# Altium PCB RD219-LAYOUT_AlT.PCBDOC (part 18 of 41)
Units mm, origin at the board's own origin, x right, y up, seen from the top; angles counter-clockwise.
Board outline 209.75 x 159.97 mm, 2 copper layers (TOP, BOTTOM), stack 0 mm thick; 398 components, 199 nets, 1469 pads, 0 vias.
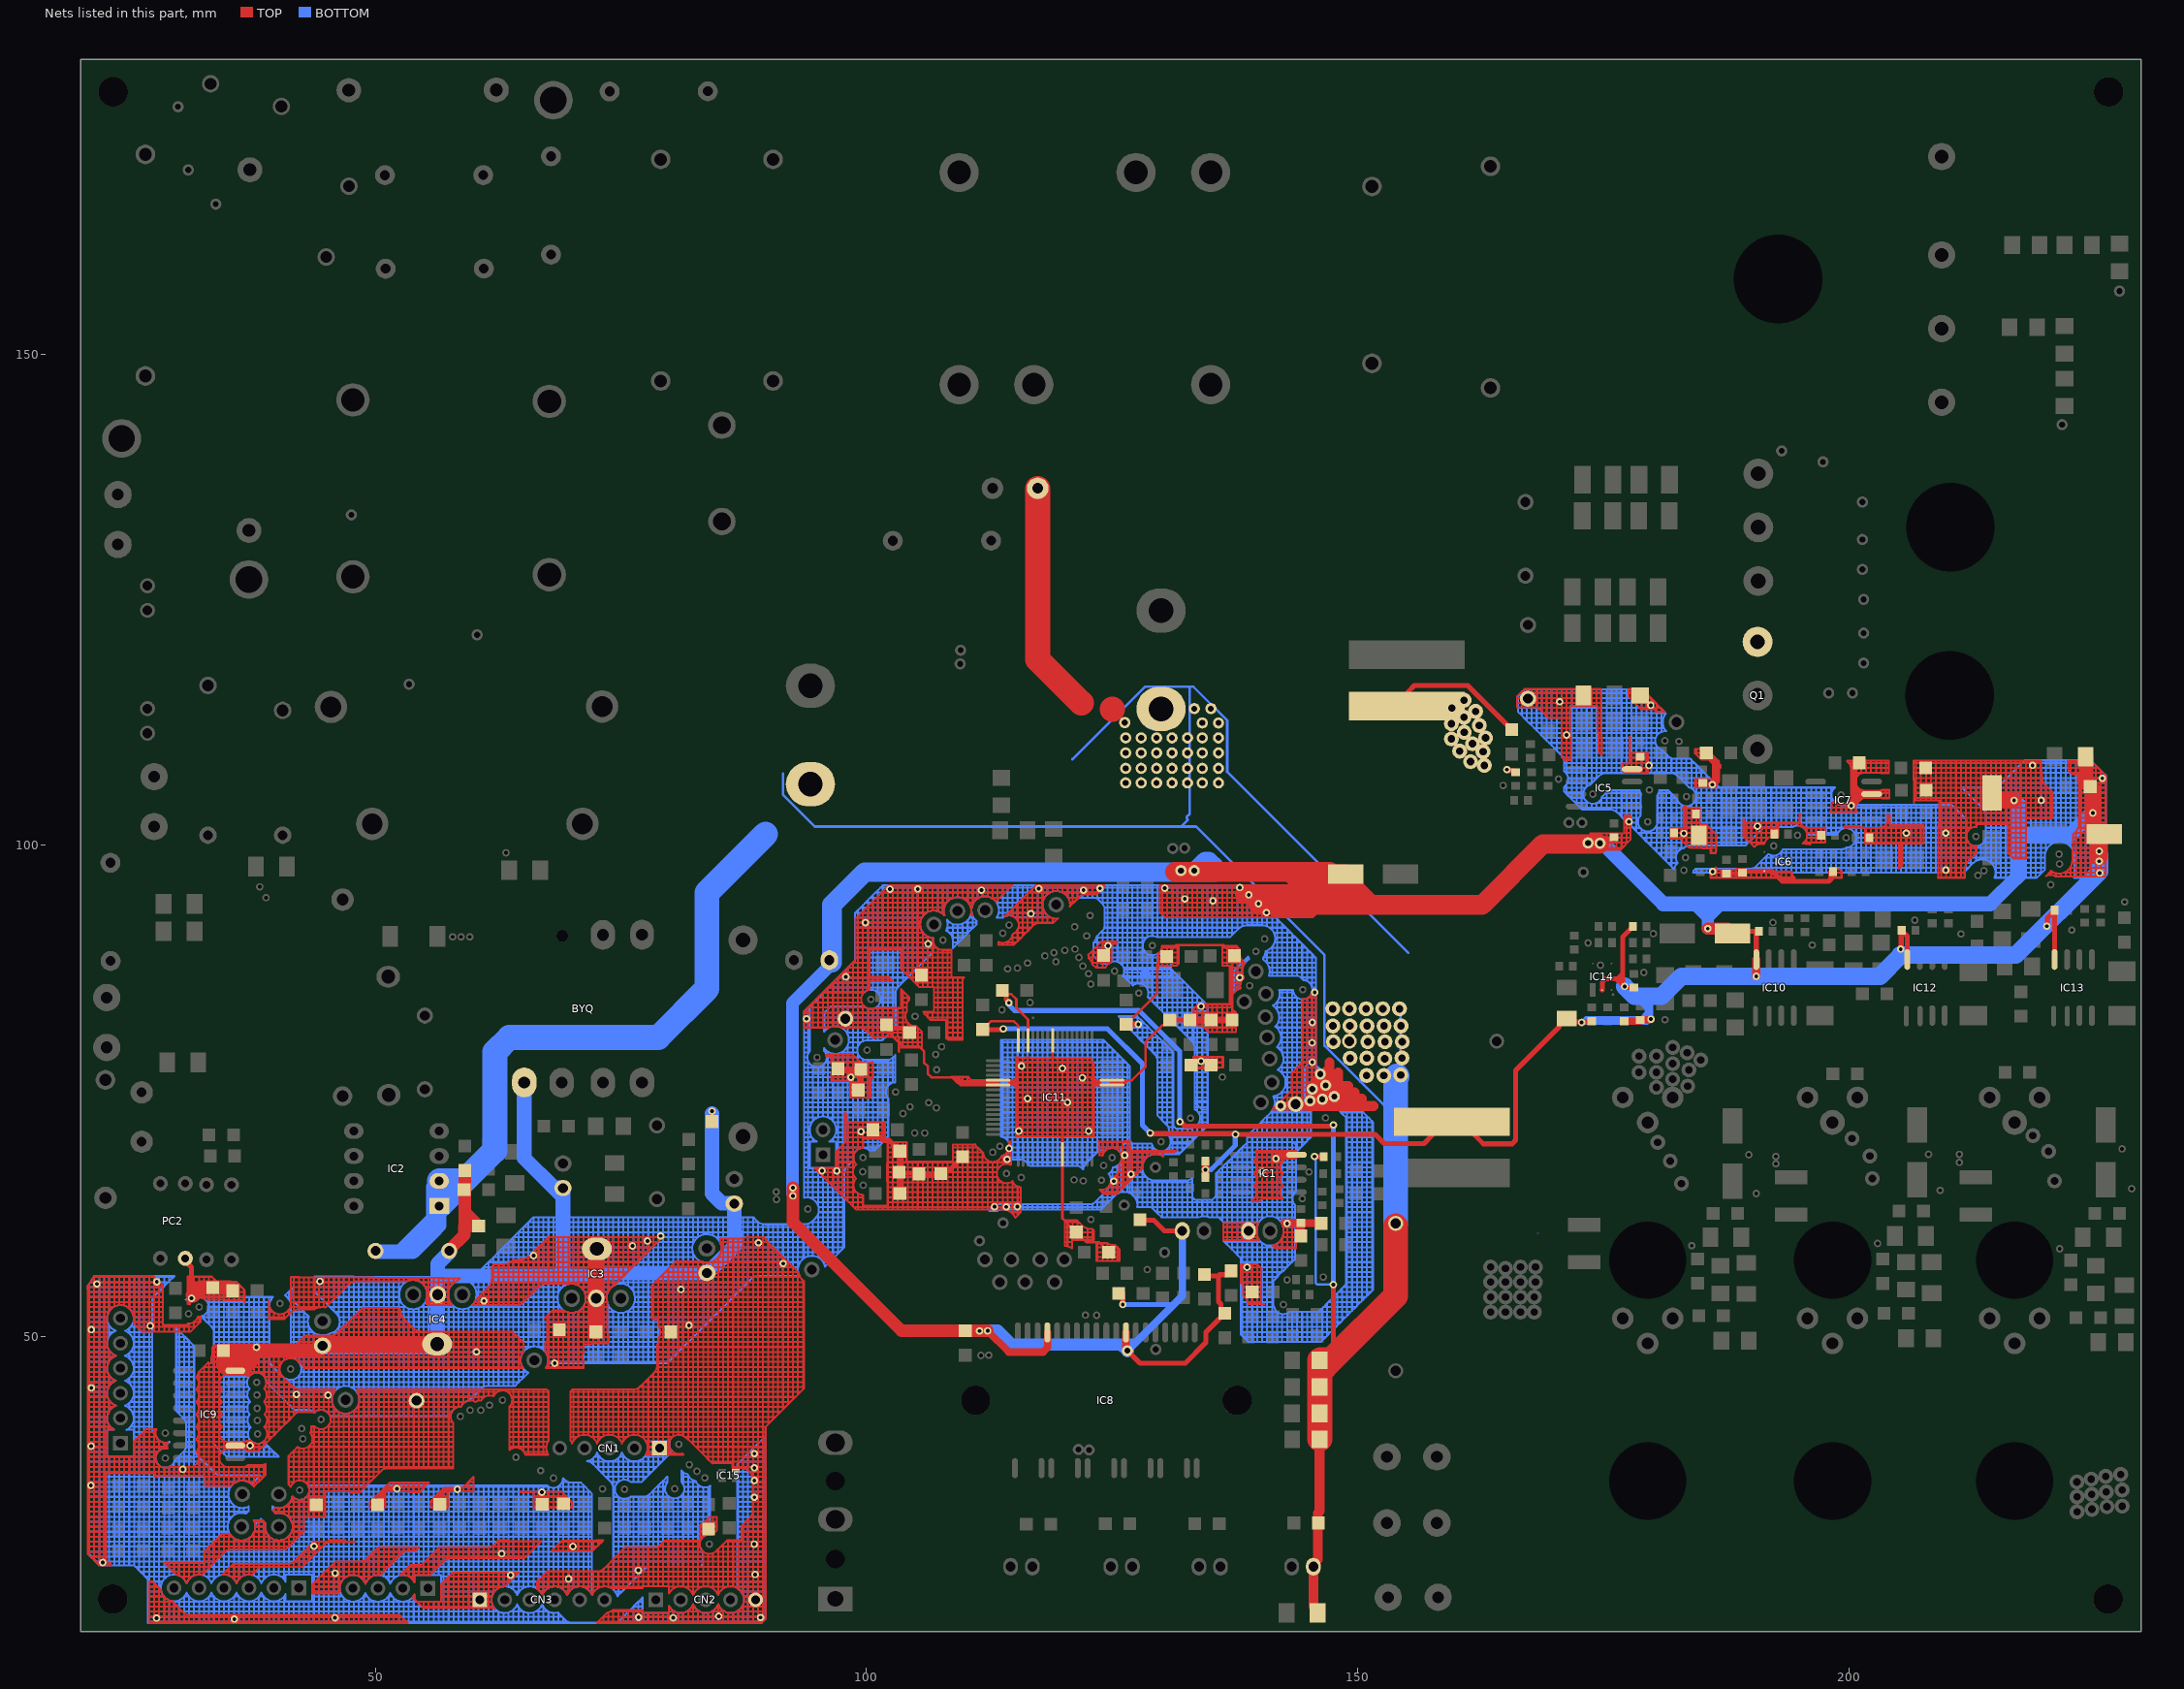
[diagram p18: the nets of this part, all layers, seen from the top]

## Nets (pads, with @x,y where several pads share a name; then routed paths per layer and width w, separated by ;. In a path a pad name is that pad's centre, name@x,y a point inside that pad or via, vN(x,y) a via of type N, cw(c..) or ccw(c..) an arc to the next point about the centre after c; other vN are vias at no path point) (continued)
GND: (continued)
  TOP w0.203: 223.073,101.39 cw(c222.057,102.282) 223.013,101.326 ccw(c222.057,102.282) 223.073,101.39 ; 223.073,101.39 ccw(c222.057,102.282) 223.315,101.788 ; 223.073,101.39 ccw(c222.057,102.282) 223.315,101.788 ; 223.073,107.231 223.073,107.376 ; 223.073,107.231 223.309,107.231 223.309,106.868 ; 223.073,107.376 223.073,107.884 ; 223.073,107.376 223.581,107.376 ; 223.073,107.884 223.073,108.392 ; 223.073,107.884 223.581,107.884 ; 223.073,108.392 ZD4.1@223.581,108.392 ; 223.073,108.392 223.073,108.631 ; 223.073,108.631 ZD4.1@223.581,108.631 ; 223.309,106.868 223.581,106.868 ; 223.315,101.788 ccw(c222.057,102.282) 223.409,102.282 ; 223.315,101.788 ccw(c222.057,102.282) 223.409,102.282 ; 223.315,101.788 223.581,101.788 ; 223.354,106.36 cw(c222.057,105.979) 223.409,105.979 ; 223.354,106.36 ccw(c222.057,105.979) 223.31,106.485 cw(c222.057,105.979) 223.354,106.36 ; 223.354,106.36 cw(c222.057,105.979) 223.409,105.979 ; 223.354,106.36 223.581,106.36 ; 223.409,102.282 223.409,102.296 ; 223.409,102.296 223.409,102.804 ; 223.409,102.296 223.581,102.296 ; 223.409,102.804 223.581,102.804 ; 223.409,102.804 223.409,103.312 ; 223.409,103.312 223.581,103.312 ; 223.409,103.312 223.409,103.82 ; 223.409,103.82 223.581,103.82 ; 223.409,103.82 223.409,104.328 ; 223.409,104.328 223.581,104.328 ; 223.409,104.328 223.409,104.836 ; 223.409,104.836 223.581,104.836 ; 223.409,104.836 223.409,105.344 ; 223.409,105.344 223.409,105.852 ; 223.409,105.344 223.581,105.344 ; 223.409,105.852 223.581,105.852 ; 223.409,105.852 223.409,105.979 ; 223.581,96.853 224.089,96.853 ; 223.581,96.853 223.581,97.216 ; 223.581,97.216 223.581,97.724 ; 223.581,97.216 224.089,97.216 ; 223.581,97.724 223.581,98.232 ; 223.581,97.724 224.089,97.724 ; 223.581,98.232 223.581,98.74 ; 223.581,98.232 224.089,98.232 ; 223.581,98.74 224.089,98.74 ; 223.581,98.74 223.581,99.248 ; 223.581,99.248 224.089,99.248 ; 223.581,99.248 223.581,99.756 ; 223.581,99.756 223.581,100.264 ; 223.581,99.756 224.089,99.756 ; 223.581,100.264 223.581,100.772 ; 223.581,100.264 224.089,100.264 ; 223.581,100.772 223.581,101.28 ; 223.581,100.772 224.089,100.772 ; 223.581,101.28 223.581,101.788 ; 223.581,101.28 224.089,101.28 ; 223.581,101.788 223.581,102.296 ; 223.581,101.788 224.089,101.788 ; 223.581,102.296 223.581,102.804 ; 223.581,102.296 224.089,102.296 ; 223.581,102.804 223.581,103.312 ; 223.581,102.804 224.089,102.804 ; 223.581,103.312 223.581,103.82 ; 223.581,103.312 224.089,103.312 ; 223.581,103.82 223.581,104.328 ; 223.581,103.82 224.089,103.82 ; 223.581,104.328 223.581,104.836 ; 223.581,104.328 224.089,104.328 ; 223.581,104.836 223.581,105.344 ; 223.581,104.836 224.089,104.836 ; 223.581,105.344 223.581,105.852 ; 223.581,105.344 C57.2@224.089,105.344 ; 223.581,105.852 223.581,106.36 ; 223.581,105.852 C57.2@224.089,105.852 ; 223.581,106.36 223.581,106.868 ; 223.581,106.36 C57.2@224.089,106.36 ; 223.581,106.868 223.581,107.376 ; 223.581,106.868 224.089,106.868 ; 223.581,107.376 223.581,107.884 ; 223.581,107.376 224.089,107.376 ; 223.581,107.884 ZD4.1@223.581,108.392 ; 223.581,107.884 224.089,107.884 ; ZD4.1@223.581,108.392 ZD4.1@223.581,108.631 ; ZD4.1@223.581,108.392 ZD4.1@224.089,108.392 ; ZD4.1@223.581,108.631 ZD4.1@224.089,108.631 ; 224.089,96.853 224.597,96.853 ; 224.089,96.853 224.089,97.216 ; 224.089,97.216 224.089,97.724 ; 224.089,97.216 224.597,97.216 ; 224.089,97.724 224.089,98.232 ; 224.089,97.724 224.597,97.724 ; 224.089,98.232 224.089,98.74 ; 224.089,98.232 224.597,98.232 ; 224.089,98.74 224.597,98.74 ; 224.089,98.74 224.089,99.248 ; 224.089,99.248 224.597,99.248 ; 224.089,99.248 224.089,99.756 ; 224.089,99.756 224.089,100.264 ; 224.089,99.756 224.597,99.756 ; 224.089,100.264 224.089,100.772 ; 224.089,100.264 EC12.2@224.597,100.264 ; 224.089,100.772 224.089,101.28 ; 224.089,100.772 EC12.2@224.597,100.772 ; 224.089,101.28 224.089,101.788 ; 224.089,101.28 EC12.2@224.597,101.28 ; 224.089,101.788 224.089,102.296 ; 224.089,101.788 EC12.2@224.597,101.788 ; 224.089,102.296 224.089,102.804 ; 224.089,102.296 224.597,102.296 ; 224.089,102.804 224.089,103.312 ; 224.089,102.804 224.597,102.804 ; 224.089,103.312 224.089,103.82 ; 224.089,103.312 pad.@224.597,103.312 ; 224.089,103.82 224.089,104.328 ; 224.089,103.82 224.597,103.82 ; 224.089,104.328 224.089,104.836 ; 224.089,104.328 224.597,104.328 ; 224.089,104.836 C57.2@224.089,105.344 ; 224.089,104.836 224.597,104.836 ; C57.2@224.089,105.344 C57.2@224.089,105.852 ; C57.2@224.089,105.344 C57.2@224.597,105.344 ; C57.2@224.089,105.852 C57.2@224.597,105.852 ; C57.2@224.089,105.852 C57.2@224.089,106.36 ; C57.2@224.089,106.36 224.089,106.868 ; C57.2@224.089,106.36 224.165,106.36 C57.2@224.597,106.36 ; 224.089,106.868 224.089,107.376 ; 224.089,106.868 224.12,106.868 224.597,106.868 ; 224.089,107.376 224.089,107.884 ; 224.089,107.376 224.12,107.376 224.597,107.376 ; 224.089,107.884 ZD4.1@224.089,108.392 ; 224.089,107.884 224.12,107.884 224.597,107.884 ; ZD4.1@224.089,108.392 224.12,108.392 ZD4.1@224.597,108.392 ; ZD4.1@224.089,108.392 ZD4.1@224.089,108.631 ; ZD4.1@224.089,108.631 224.12,108.631 ZD4.1@224.597,108.631 ; 224.597,96.853 225.105,96.853 ; 224.597,96.853 224.597,97.216 ; 224.597,97.216 224.597,97.724 ; 224.597,97.216 225.105,97.216 ; 224.597,97.724 224.597,98.232 ; 224.597,97.724 225.105,97.724 ; 224.597,98.232 224.597,98.74 ; 224.597,98.232 225.105,98.232 ; 224.597,98.74 224.597,99.248 ; 224.597,98.74 225.105,98.74 ; 224.597,99.248 225.105,99.248 ; 224.597,99.248 224.597,99.756 ; 224.597,99.756 EC12.2@224.597,100.264 ; 224.597,99.756 225.105,99.756 ; EC12.2@224.597,100.264 EC12.2@224.597,100.772 ; EC12.2@224.597,100.264 EC12.2@225.105,100.264 ; EC12.2@224.597,100.772 EC12.2@225.105,100.772 ; EC12.2@224.597,100.772 EC12.2@224.597,101.28 ; EC12.2@224.597,101.28 EC12.2@224.597,101.788 ; EC12.2@224.597,101.28 225.073,101.28 EC12.2@225.105,101.28 ; EC12.2@224.597,101.788 224.597,102.296 ; EC12.2@224.597,101.788 224.95,101.788 EC12.2@225.105,101.788 ; 224.597,102.296 224.597,102.804 ; 224.597,102.296 224.95,102.296 225.105,102.296 ; 224.597,102.804 224.95,102.804 225.105,102.804 ; 224.597,102.804 pad.@224.597,103.312 ; pad.@224.597,103.312 224.597,103.82 ; pad.@224.597,103.312 224.95,103.312 pad.@225.105,103.312 ; 224.597,103.82 224.597,104.328 ; 224.597,103.82 224.95,103.82 225.105,103.82 ; 224.597,104.328 224.95,104.328 225.105,104.328 ; 224.597,104.328 224.597,104.836 ; 224.597,104.836 C57.2@224.597,105.344 ; 224.597,104.836 224.95,104.836 225.105,104.836 ; C57.2@224.597,105.344 C57.2@224.597,105.852 ; C57.2@224.597,105.344 224.95,105.344 C57.2@225.105,105.344 ; C57.2@224.597,105.852 224.597,105.928 C57.2@224.597,106.36 ; C57.2@224.597,105.852 224.673,105.852 C57.2@225.105,105.852 ; C57.2@224.597,106.36 224.597,106.868 ; C57.2@224.597,106.36 C57.2@225.105,106.36 ; 224.597,106.868 224.597,107.376 ; 224.597,106.868 225.105,106.868 ; 224.597,107.376 224.597,107.884 ; 224.597,107.376 225.105,107.376 ; 224.597,107.884 ZD4.1@224.597,108.392 ; 224.597,107.884 225.105,107.884 ; ZD4.1@224.597,108.392 ZD4.1@224.597,108.631 ; ZD4.1@224.597,108.392 ZD4.1@224.851,108.392 ; ZD4.1@224.597,108.631 224.612,108.631 ZD4.1@224.851,108.392 ; ZD4.1@224.851,108.392 225.105,108.138 ; 225.105,96.853 pad.@225.613,96.853 ; 225.105,96.853 225.105,97.216 ; 225.105,97.216 225.105,97.724 ; 225.105,97.216 pad.@225.613,97.216 ; 225.105,97.724 225.105,98.232 ; 225.105,97.724 225.613,97.724 ; 225.105,98.232 pad.@225.613,98.232 ; 225.105,98.232 225.105,98.74 ; 225.105,98.74 225.105,99.248 ; 225.105,98.74 225.613,98.74 ; 225.105,99.248 225.441,99.248 pad.@225.613,99.248 ; 225.105,99.248 225.105,99.756 ; 225.105,99.756 225.441,99.756 225.613,99.756 ; 225.105,99.756 EC12.2@225.105,100.264 ; EC12.2@225.105,100.264 225.441,100.264 EC12.2@225.613,100.264 ; EC12.2@225.105,100.264 EC12.2@225.105,100.772 ; EC12.2@225.105,100.772 225.441,100.772 EC12.2@225.613,100.772 ; EC12.2@225.105,100.772 225.105,101.248 EC12.2@225.105,101.28 ; EC12.2@225.105,101.28 EC12.2@225.613,101.28 ; EC12.2@225.105,101.28 EC12.2@225.105,101.788 ; EC12.2@225.105,101.788 EC12.2@225.613,101.788 ; EC12.2@225.105,101.788 225.105,102.296 ; 225.105,102.296 225.613,102.296 ; 225.105,102.296 225.105,102.804 ; 225.105,102.804 225.613,102.804 ; 225.105,102.804 pad.@225.105,103.312 ; pad.@225.105,103.312 225.105,103.82 ; pad.@225.105,103.312 225.613,103.312 ; 225.105,103.82 225.105,104.328 ; 225.105,103.82 225.613,103.82 ; 225.105,104.328 225.105,104.836 ; 225.105,104.328 225.613,104.328 ; 225.105,104.836 C57.2@225.105,105.344 ; 225.105,104.836 225.613,104.836 ; C57.2@225.105,105.344 C57.2@225.105,105.852 ; C57.2@225.105,105.344 225.613,105.344 ; C57.2@225.105,105.852 225.613,105.852 ; C57.2@225.105,105.852 C57.2@225.105,106.36 ; C57.2@225.105,106.36 225.613,106.36 ; C57.2@225.105,106.36 225.105,106.868 ; 225.105,106.868 pad.@225.613,106.868 ; 225.105,106.868 225.105,107.376 ; 225.105,107.376 225.105,107.884 ; 225.105,107.376 225.613,107.376 ; 225.105,107.884 225.105,108.138 ; 225.105,107.884 225.359,107.884 ; 225.105,108.138 225.359,107.884 ; 225.359,107.884 225.613,107.63 ; pad.@225.613,96.853 226.012,96.853 226.121,96.962 226.121,97.216 ; pad.@225.613,96.853 pad.@225.613,97.216 ; pad.@225.613,97.216 225.613,97.724 ; pad.@225.613,97.216 226.121,97.216 ; 225.613,97.724 pad.@225.613,98.232 ; 225.613,97.724 226.121,97.724 ; pad.@225.613,98.232 226.121,98.232 ; pad.@225.613,98.232 225.613,98.74 ; 225.613,98.74 pad.@225.613,99.248 ; 225.613,98.74 226.121,98.74 ; pad.@225.613,99.248 226.121,99.248 ; pad.@225.613,99.248 225.613,99.756 ; 225.613,99.756 EC12.2@225.613,100.264 ; 225.613,99.756 226.121,99.756 ; EC12.2@225.613,100.264 EC12.2@225.613,100.772 ; EC12.2@225.613,100.264 EC12.2@226.121,100.264 ; EC12.2@225.613,100.772 225.613,101.153 EC12.2@225.613,101.28 ; EC12.2@225.613,100.772 EC12.2@226.121,100.772 ; EC12.2@225.613,101.28 EC12.2@225.613,101.788 ; EC12.2@225.613,101.28 EC12.2@226.121,101.28 ; EC12.2@225.613,101.788 225.613,102.296 ; EC12.2@225.613,101.788 EC12.2@226.121,101.788 ; 225.613,102.296 225.613,102.804 ; 225.613,102.296 226.121,102.296 ; 225.613,102.804 225.613,103.312 ; 225.613,102.804 226.121,102.804 ; 225.613,103.312 225.613,103.82 ; 225.613,103.312 226.121,103.312 ; 225.613,103.82 225.613,104.328 ; 225.613,103.82 226.121,103.82 ; 225.613,104.328 225.613,104.836 ; 225.613,104.328 226.121,104.328 ; 225.613,104.836 225.613,105.344 ; 225.613,104.836 226.121,104.836 ; 225.613,105.344 225.613,105.852 ; 225.613,105.344 226.121,105.344 ; 225.613,105.852 225.613,106.36 ; 225.613,105.852 226.121,105.852 ; 225.613,106.36 pad.@225.613,106.868 ; 225.613,106.36 226.121,106.36 ; pad.@225.613,106.868 225.613,107.376 ; pad.@225.613,106.868 pad.@226.121,106.868 ; 225.613,107.376 225.613,107.63 ; 225.613,107.376 225.867,107.376 ; 225.613,107.63 225.867,107.376 ; 225.867,107.376 226.121,107.122 ; 226.121,97.216 226.121,97.724 ; 226.121,97.724 226.121,98.232 ; 226.121,98.232 226.121,98.74 ; 226.121,98.74 226.121,99.248 ; 226.121,99.248 226.121,99.756 ; 226.121,99.756 EC12.2@226.121,100.264 ; 226.121,99.756 EC12.2@226.121,100.264 ; EC12.2@226.121,100.264 EC12.2@226.121,100.772 ; EC12.2@226.121,100.264 EC12.2@226.121,100.772 ; EC12.2@226.121,100.772 226.121,101.153 EC12.2@226.121,101.28 ; EC12.2@226.121,100.772 EC12.2@226.121,101.28 ; EC12.2@226.121,101.28 EC12.2@226.121,101.788 ; EC12.2@226.121,101.28 EC12.2@226.121,101.788 ; EC12.2@226.121,101.788 226.121,102.296 ; EC12.2@226.121,101.788 226.121,102.296 ; 226.121,102.296 226.121,102.804 ; 226.121,102.296 226.121,102.804 ; 226.121,102.804 226.121,103.312 ; 226.121,102.804 226.121,103.312 ; 226.121,103.312 226.121,103.82 ; 226.121,103.312 226.121,103.82 ; 226.121,103.82 226.121,104.328 ; 226.121,103.82 226.121,104.328 ; 226.121,104.328 226.121,104.836 ; 226.121,104.328 226.121,104.836 ; 226.121,104.836 226.121,105.344 ; 226.121,104.836 226.121,105.344 ; 226.121,105.344 226.121,105.852 ; 226.121,105.344 226.121,105.852 ; 226.121,105.852 226.121,106.36 ; 226.121,105.852 226.121,106.36 ; 226.121,106.36 226.121,106.822 pad.@226.121,106.868 ; 226.121,106.36 pad.@226.121,106.868 ; pad.@226.121,106.868 226.121,107.122 ; pad.@226.121,106.868 226.121,107.122
  TOP w0.254: IC9.2@35.748,38.923 36.129,38.923 36.637,38.923 37.145,38.923 pad.@37.272,38.923 ; IC15.3@86.675,36.375 86.675,36.652 86.675,36.721 ; C98.2@102.042,81.722 102.169,81.595 102.296,81.468 102.367,81.397 102.367,80.96 102.367,80.84 102.677,80.53 102.722,80.484 103.294,79.913 103.644,79.563 103.693,79.563 104.201,79.563 104.709,79.563 105.217,79.563 105.344,79.563 105.471,79.436 105.489,79.418 105.852,79.055 105.852,77.912 106.233,77.531 106.233,76.769 106.614,76.388 108.66,76.388 ; 108.773,76.388 109.154,76.007 ; 109.027,76.388 109.281,76.134 109.408,76.007 ; 109.281,76.388 109.662,76.007 ; 110.707,76.091 IC11.21@113.387,76.091 ; C78.2@111.821,81.265 112.659,82.103 114.996,82.103 115.437,81.662 IC11.16@115.437,80.156 ; IC11.21@113.387,76.106 IC11.21@113.387,76.091 ; C36.2@113.828,85.227 C36.2@114.224,84.831 ; C36.2@114.234,84.948 114.329,84.853 114.734,84.853 115.25,84.337 115.25,83.451 116.437,82.264 IC11.14@116.437,80.156 ; 115.25,75.626 115.03,75.626 IC11.22@113.407,75.626 ; 115.25,76.007 115.166,76.091 115.034,76.091 IC11.21@113.387,76.091 ; 118.937,77.535 118.937,77.912 118.937,78.42 IC11.9@118.937,80.156 ; 119.937,73.677 119.937,73.34 119.937,72.832 119.937,72.324 119.937,71.816 119.937,71.308 119.937,70.8 119.937,70.292 119.937,70.217 IC11.42@119.937,68.556 119.937,62.049 120.166,61.82 120.33,61.656 120.457,61.529 120.838,61.148 120.965,61.021 C64.2@121.346,60.64 121.473,60.513 121.854,60.132 121.981,60.005 122.126,59.86 122.362,59.624 123.632,59.624 123.741,59.515 124.013,59.243 124.14,59.116 124.521,58.735 C35.1@124.648,58.608 C35.1@125.029,58.227 ; 122.87,76.261 122.997,76.134 123.025,76.106 123.326,76.106 IC11.60@124.987,76.106 ; 122.997,75.626 123.017,75.606 123.326,75.606 IC11.59@124.987,75.606 ; 125.902,75.864 IC11.60@126.144,76.106 ; 126.132,75.857 126.299,76.023 126.299,76.106 ; C38.1@126.564,81.635 C38.1@126.426,81.773 126.44,81.787 129.601,84.948 129.601,87.469 129.601,87.945 129.682,88.026 129.728,88.072 130.109,88.453 130.236,88.58 130.617,88.961 130.744,89.088 131.125,89.469 131.252,89.596 131.412,89.756 131.506,89.85 136.358,89.85 136.452,89.756 136.612,89.596 136.713,89.495 136.926,89.282 137.12,89.088 137.221,88.987 C44.2@137.449,88.759 ; 126.807,69.133 127.045,68.895 127.061,68.879 127.077,68.863 ; C42.1@130.871,82.23 130.348,81.707 130.118,81.707 128.382,79.971 128.382,77.468 127.02,76.106 126.587,76.106 ; C43.1@132.903,82.23 133.284,82.23 133.665,82.23 134.173,82.23 134.681,82.23 C40.1@135.062,82.23 135.189,82.23 135.697,82.23 136.205,82.23 136.713,82.23 C41.1@137.221,82.23 137.221,82.484 137.221,82.992 137.221,83.423 137.221,84.767 137.221,85.024 137.221,85.532 137.221,86.04 137.221,86.548 137.221,87.056 137.221,87.564 137.221,88.072 C44.2@137.221,88.25 ; R115.1@146.477,68.284 R115.1@146.511,68.318 ; 148.016,76.261 148.778,75.499 149.413,74.864 150.048,74.229 150.81,73.467 ; C91.1@178.687,82.167 C91.1@178.75,82.23 ; 109.154,76.007 109.281,76.007 109.408,76.007 ; 109.154,76.007 109.281,75.88 109.312,75.849 ; 109.312,75.849 109.789,75.849 110.297,75.849 110.805,75.849 112.172,75.849 112.741,75.849 ; 109.312,75.849 109.326,75.835 109.555,75.606 IC11.22@113.387,75.606 IC11.22@113.407,75.626 ; 109.408,76.007 109.662,76.007 ; 109.662,76.007 109.789,76.007 110.297,76.007 110.805,76.007 110.807,76.007 IC11.21@112.583,76.007 ; IC11.21@112.583,76.007 112.933,76.007 113.091,75.849 ; IC11.21@112.583,76.007 112.741,75.849 ; 112.741,75.849 112.936,75.655 112.964,75.626 IC11.22@113.388,75.626 ; 112.741,75.849 113.091,75.849 ; 113.091,75.849 113.387,75.849 ; 113.387,75.849 IC11.21@113.387,76.091 ; 113.387,75.849 113.387,75.627 IC11.22@113.388,75.626 ; IC11.22@113.388,75.626 IC11.22@113.407,75.626 ; IC11.59@124.987,75.606 126.087,75.606 126.358,75.877 126.587,76.106 ; IC11.59@124.987,75.606 124.987,75.864 IC11.60@124.987,76.106 ; IC11.60@124.987,76.106 IC11.60@126.144,76.106 ; IC11.60@126.144,76.106 126.299,76.106 ; 126.299,76.106 126.587,76.106 ; C44.2@137.221,88.25 137.551,88.58 pad.@137.59,88.618 C44.2@137.449,88.759 ; C44.2@137.221,88.25 137.221,88.531 137.271,88.58 C44.2@137.449,88.759
  TOP w0.5: R1.1@155.093,115.607 155.752,116.266 161.224,116.266 161.224,116.215 R3.1@165.669,111.77
  TOP w0.508: PC2.K@30.668,57.973 30.668,57.698 31.303,57.063 31.303,56.132 31.303,56.068 31.303,55.56 31.303,55.052 31.303,54.544 31.303,54.036 pad.@31.303,53.909 ; R74.1@50.226,32.903 50.353,33.03 50.531,33.208 50.564,33.241 50.564,33.716 50.564,33.927 50.861,34.224 51.124,34.487 51.369,34.487 51.877,34.487 52.154,34.487 pad.@52.203,34.535 ; R76.1@56.567,32.95 56.786,33.169 56.786,33.208 56.786,33.716 56.786,34.18 56.83,34.224 56.957,34.351 57.084,34.478 57.465,34.478 57.973,34.478 pad.@58.354,34.478 ; C39.2@84.262,71.892 84.272,71.902 84.272,72.937 pad.@84.281,72.947 ; R144.1@97.089,77.277 97.125,77.241 97.597,77.241 98.105,77.241 98.613,77.241 99.121,77.241 99.378,77.241 C99.2@99.414,77.204 99.283,77.073 99.283,76.896 99.283,76.388 99.283,75.88 99.283,75.372 99.283,75.229 C88.2@99.151,75.097 ; C12.2@100.645,71.054 100.899,70.8 101.153,70.546 101.407,70.292 101.552,70.147 101.722,69.977 102.3,69.977 102.305,69.972 102.311,69.972 102.481,69.802 102.499,69.784 102.677,69.606 103.007,69.276 103.185,69.098 103.35,68.933 C70.2@103.35,68.857 ; C98.2@102.367,81.397 102.677,81.397 103.185,81.397 103.693,81.397 103.942,81.397 104.201,81.138 C37.1@104.379,80.96 ; C72.2@103.388,64.577 103.35,64.615 103.35,64.704 103.35,65.212 103.35,65.72 103.35,66.228 C73.2@103.35,66.698 ; C70.2@103.388,68.895 C70.2@103.35,68.857 ; C28.2@109.789,68.311 109.738,68.26 109.281,67.803 109.23,67.752 108.773,67.295 108.722,67.244 108.483,67.004 108.265,67.004 107.946,67.004 107.757,66.816 107.677,66.736 C69.2@107.55,66.608 107.534,66.592 107.249,66.592 106.741,66.592 106.233,66.592 105.725,66.592 105.35,66.592 C71.2@105.334,66.576 105.254,66.656 105.217,66.656 104.709,66.656 104.201,66.656 103.693,66.656 103.392,66.656 C73.2@103.35,66.698 ; C78.2@111.821,81.265 111.846,81.239 113.768,81.239 113.856,81.327 pad.@113.925,81.327 ; C36.2@114.224,84.831 114.224,84.309 114.487,84.045 pad.@114.487,83.976 ; 124.987,75.864 125.902,75.864 ; C97.1@125.702,54.811 125.88,54.633 126.096,54.417 126.087,54.408 126.087,53.292 pad.@126.078,53.283 ; C38.1@126.44,81.787 pad.@127.655,81.787 ; pad.@126.553,48.575 127.823,47.305 132.441,47.305 134.554,49.418 134.554,50.473 C84.2@136.463,52.382 ; C100.1@127.823,61.91 127.873,61.86 129.235,61.86 130.328,60.767 EC7.2@132.141,60.767 ; pad.@128.877,70.723 128.926,70.674 129.105,70.674 129.118,70.661 137.313,70.661 137.328,70.646 137.508,70.646 pad.@137.557,70.597 ; C42.1@130.871,82.23 C43.1@132.903,82.23 ; pad.@131.897,71.882 131.966,71.882 132.415,71.433 147.339,71.433 147.454,71.548 pad.@147.522,71.548 ; C81.1@134.681,56.449 134.935,56.195 135.824,56.195 ; C84.2@136.526,52.445 136.4,52.445 136.067,52.778 136.067,53.33 135.824,53.573 135.824,56.195 ; R54.2@137.094,56.703 136.698,56.307 135.936,56.307 135.824,56.195 ; pad.@137.634,70.606 151.767,70.606 152.709,69.663 156.743,69.663 R95.2@157.592,70.511 ; 141.412,92.898 141.454,92.856 145.393,92.856 146.492,93.955 ; pad.@142.809,61.529 142.84,61.56 143.317,61.56 143.698,61.56 144.175,61.56 C46.2@144.206,61.591 ; pad.@145.598,68.345 145.612,68.332 146.429,68.332 R115.1@146.477,68.284 ; 147.508,47.813 pad.@147.508,55.306 ; R95.2@161.7,70.705 162.773,69.632 165.706,69.632 166.068,69.994 166.068,77.1 170.511,81.542 170.511,81.83 171.057,82.376 D25.1@171.257,82.376 171.615,82.018 173.712,82.018 C79.1@173.797,82.103 ; pad.@165.183,107.708 165.252,107.708 165.373,107.587 165.904,107.587 R8.2@166.05,107.441 ; pad.@172.721,81.977 pad.@172.789,81.977 ; pad.@174.657,100.219 174.813,100.219 174.829,100.219 174.874,100.264 175.298,100.688 175.321,100.688 175.829,100.688 175.937,100.688 176.021,100.772 C15.1@176.083,100.834 ; IC14.2@174.874,85.278 174.891,85.295 174.891,86.123 175.188,86.421 176.337,86.421 ; pad.@176.948,85.81 176.337,86.421 ; pad.@177.158,85.649 176.972,85.834 176.972,86.548 ; pad.@177.215,85.543 178.104,85.543 C89.1@178.115,85.532 ; C68.1@177.985,91.755 177.985,91.705 176.961,90.681 176.961,86.918 ; R14.1@187.506,97.13 187.513,97.13 188.021,97.13 188.529,97.13 189.037,97.13 C14.1@189.169,97.13 ; EC20.2@188.91,91.263 190.796,91.263 C58.2@190.812,91.247 190.812,91.197 190.561,90.946 IC10.4@190.561,88.382 ; C14.1@189.169,97.216 C14.1@189.315,97.362 ; C14.1@189.315,97.384 189.545,97.384 189.834,97.384 IC6.4@191.38,97.384 192.171,97.384 192.25,97.305 192.339,97.216 192.593,96.962 192.847,96.708 192.974,96.581 193.222,96.333 197.929,96.333 198.227,96.631 198.227,96.708 198.227,97.197 198.246,97.216 C18.1@198.373,97.343 ; C16.1@192.401,101.153 192.401,101.1 C16.1@192.544,100.957 ; pad.@205.304,89.397 pad.@205.255,89.446 205.304,89.494 205.304,91.323 C74.2@205.355,91.374 205.355,91.324 205.928,90.751 IC12.4@205.928,88.382 ; pad.@220.131,91.776 220.18,91.824 220.18,92.625 220.911,93.356 C76.2@220.911,93.406 ; C76.2@220.883,93.378 C76.2@220.911,93.406 ; IC13.4@220.896,88.4 IC13.4@220.913,88.384 ; IC13.4@220.914,88.382 IC13.4@220.913,88.384 ; C73.2@103.35,66.698 C73.2@103.312,66.736 103.35,66.774 103.35,67.244 103.35,67.752 103.35,68.26 103.35,68.768 C70.2@103.35,68.857 ; 176.337,86.421 176.464,86.421 ; 176.464,86.421 176.961,86.918 ; 176.464,86.421 176.845,86.421 176.972,86.548 ; 176.961,86.918 176.972,86.929 176.972,86.548 ; C76.2@220.911,93.406 220.913,93.404 IC13.4@220.913,88.384
  TOP w0.762: pad.@111.507,50.596 pad.@111.51,50.599 ; pad.@112.327,50.596 114.475,48.448 117.979,48.448 118.425,48.894 IC8.16@118.425,50.418 ; IC8.8@126.406,50.437 126.397,50.428 126.397,48.834 126.553,48.678 pad.@126.553,48.575 ; R113.1@134.489,66.228 R116.1@134.489,67.879 ; pad.@141.666,68.133 141.793,68.26 142.047,68.514 142.301,68.514 142.809,68.514 143.317,68.514 143.698,68.514 IC1.4@143.754,68.514 ; C86.2@144.206,60.259 C46.2@144.206,61.591 144.225,61.572 146.246,61.572 R98.2@146.289,61.529 ; R147.1@177.099,82.103 C91.1@178.75,82.103 ; C91.1@178.75,82.211 178.76,82.221 178.788,82.249 179.778,82.249 pad.@179.842,82.312 ; pad.@200.22,104.049 pad.@200.467,104.296 ; C21.1@201.051,108.392 200.721,108.062 200.543,107.884 200.467,107.808 200.467,107.376 200.467,106.868 200.467,106.36 200.467,105.852 ; IC7.3@203.007,105.217 202.753,105.217 IC7.3@202.301,105.217 202.245,105.217 201.737,105.217 201.229,105.217 201.102,105.217 ; pad.@200.467,104.296 200.467,104.328 200.467,104.836 200.467,105.344 200.467,105.852 ; pad.@200.467,104.296 200.499,104.328 200.721,104.55 201.007,104.836 201.102,104.931 201.102,105.217 ; 200.467,105.852 200.721,105.598 200.975,105.344 201.102,105.217
  TOP w0.8: C9.1@185.481,109.408 186.258,108.631 186.497,108.392 186.497,107.884 186.497,107.862 186.497,106.601 186.489,106.593 186.256,106.36 pad.@186.082,106.186 ; EC20.2@187.651,91.535 EC20.2@188.14,91.046 ; pad.@190.561,86.675 IC10.4@190.561,88.382
  TOP w1: D20.1@146.111,21.905 145.476,22.54 EC19.2@145.476,26.604 145.476,26.889 145.933,27.347 145.933,32.065 146.114,32.246 R59.1@146.114,39.558
  TOP w1.016: pad.@144.968,73.467 145.229,73.467 150.81,73.467 151.572,73.467 ; pad.@145.212,74.229 145.274,74.167 145.349,74.167 145.73,74.167 pad.@146.396,74.167 ; pad.@145.454,75.646 145.688,75.88 145.73,75.922 147.127,77.319 147.127,77.912 ; pad.@145.456,75.392 145.73,75.392 147.361,75.392 ; pad.@145.699,74.864 145.73,74.833 pad.@146.396,74.167 ; 146.363,76.176 147.296,76.176 148.016,76.896 148.016,76.261 148.016,76.047 147.468,75.499 ; 147,75.031 147.361,75.392 ; 149.032,75.499 148.778,75.499 147.468,75.499 ; 149.667,74.864 149.413,74.864 147,74.864 147,74.805 146.396,74.201 pad.@146.396,74.167 ; 150.429,74.229 150.048,74.229 147.603,74.229 147.565,74.191 146.42,74.191 pad.@146.396,74.167 ; 147.361,75.392 147.468,75.499
  TOP w1.2: pad.@185.624,91.535 EC20.2@187.651,91.535
  TOP w1.27: IC4.4@56.3,49.261 IC4.4@56.331,49.292 ; IC4.2@56.331,54.259 IC4.2@56.362,54.29 ; C63.2@57.532,58.735 57.532,58.838 59.056,60.362 59.056,61.275 ; C22.2@59.116,66.914 59.116,62.672 ; pad.@92.505,65.147 92.505,65.133 92.501,65.129 pad.@92.501,64.341 92.517,64.325 92.517,61.656 103.566,50.607 C31.2@110.043,50.607 pad.@112.316,50.607 ; R59.1@146.114,39.558 R59.1@146.128,39.572 ; 59.056,61.275 C24.2@60.513,61.275 59.116,62.672 ; 59.056,61.275 59.116,61.335 59.116,62.672
  TOP w1.5: pad.@31.462,54.237 31.557,54.332 31.769,54.544 32.065,54.84 32.227,55.001 32.573,55.001 33.081,55.001 C30.2@33.462,55.001 33.589,55.001 34.097,55.001 34.605,55.001 35.113,55.001 35.164,55.001 R49.1@35.494,54.671 ; IC4.4@56.3,49.261 56.151,49.112 55.941,49.112 55.433,49.112 54.925,49.112 54.417,49.112 53.909,49.112 53.401,49.112 52.893,49.112 52.385,49.112 51.877,49.112 51.369,49.112 50.861,49.112 50.353,49.112 49.845,49.112 49.337,49.112 48.829,49.112 48.321,49.112 47.813,49.112 47.305,49.112 46.797,49.112 46.289,49.112 45.781,49.112 45.273,49.112 44.765,49.112 44.667,49.112 EC6.2@44.638,49.083 44.534,49.083 44.407,48.956 44.257,48.806 44.026,48.575 43.749,48.575 43.241,48.575 42.733,48.575 42.225,48.575 41.717,48.575 41.209,48.575 40.701,48.575 40.193,48.575 39.685,48.575 39.177,48.575 38.669,48.575 38.161,48.575 37.653,48.575 ; R136.2@72.451,50.48 72.451,50.765 72.462,50.776 72.462,50.988 72.462,51.496 72.462,52.004 72.462,52.512 72.462,53.02 72.462,53.528 72.462,53.88 IC3.2@72.491,53.909 72.52,53.938 72.52,54.036 72.52,54.544 72.52,55.052 72.52,55.56 72.52,56.068 72.52,56.576 72.52,57.084 72.52,57.592 72.52,58.1 72.52,58.608 72.52,58.905 IC3.4@72.553,58.938 ; EC15.2@214.564,105.344 214.564,104.836 214.564,104.818 214.814,104.568 214.945,104.568 215.453,104.568 215.961,104.568 216.469,104.568 pad.@216.805,104.568 ; ZD4.1@224.07,109.027 224.12,108.977 224.12,108.631 224.12,108.392 224.12,107.884 224.12,107.376 224.12,106.868 224.12,106.405 224.165,106.36 224.597,105.928 224.673,105.852 224.95,105.575 224.95,105.344 224.95,104.836 224.95,104.328 224.95,103.82 224.95,103.312 224.95,102.804 224.95,102.296 224.95,101.788 224.95,101.403 225.073,101.28 225.105,101.248 225.2,101.153 225.541,101.153 225.613,101.153 EC12.2@226,101.153 ; 34.554,47.686 34.554,47.94 34.554,48.448 C48.2@34.554,48.575 34.605,48.575 35.113,48.575 35.621,48.575 36.129,48.575 36.637,48.575 37.145,48.575 37.653,48.575 ; 34.554,47.686 34.554,47.432 34.554,47.116 34.605,47.065 34.746,46.924 34.908,46.762 35.113,46.762 35.621,46.762 36.129,46.762 36.563,46.762 36.637,46.836 36.725,46.924 37.145,47.344 37.233,47.432 37.442,47.641 37.442,47.94 37.442,48.364 ; 34.554,47.686 34.605,47.686 35.113,47.686 35.621,47.686 36.129,47.686 36.637,47.686 36.764,47.686 37.018,47.94 37.145,48.067 37.442,48.364 ; 37.442,48.364 37.526,48.448 37.653,48.575
  TOP w1.8: 225.441,98.867 225.441,99.248 225.441,99.756 225.441,100.264 225.441,100.772 225.441,101.053 EC12.2@225.541,101.153
  TOP w2: 131.38,97.313 143.091,97.313 ; 138.491,95.056 138.745,95.056 139.253,95.056 139.254,95.056 145.349,95.056 ; pad.@139.882,93.977 139.904,93.955 140.269,93.955 140.355,93.955 146.492,93.955 148.864,93.955 ; EC17.2@148.772,97.089 147.386,97.089 147.162,97.313 145.603,97.313 ; EC17.2@148.931,96.365 151.341,93.955 ; pad.@173.332,100.147 168.855,100.147 162.662,93.955 151.341,93.955 ; pad.@173.432,100.147 pad.@174.586,100.147 ; 143.091,97.313 145.603,97.313 ; 143.091,97.313 145.349,95.056 ; 145.349,95.056 147.763,95.056 ; 145.603,97.313 145.603,97.216 147.251,95.568 147.763,95.056 ; 147.763,95.056 148.864,93.955 ; 148.864,93.955 151.341,93.955
  TOP w2.54: R106.2@117.423,136.332 117.423,118.919 121.854,114.488 ; 124.996,113.886 125.029,113.853 ; R62.1@146.117,47.596 146.2,47.679 147.24,47.679 147.257,47.696 147.391,47.696 ; R59.1@146.128,39.572 146.142,39.586 146.142,46.447 ; R62.1@146.142,47.305 146.142,46.447 ; C90.1@153.858,61.282 153.858,54.163 147.508,47.813 147.391,47.696 ; 146.142,46.447 147.391,47.696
